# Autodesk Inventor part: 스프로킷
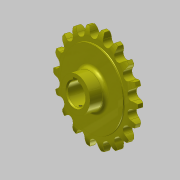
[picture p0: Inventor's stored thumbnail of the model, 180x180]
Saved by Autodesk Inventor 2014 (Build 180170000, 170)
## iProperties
Created: 2016-03
Part Number: 스프로킷
Material: 강철, 탄소
Document SubType Name: Modeling
Designer: mduedu
Density: 7.87 g/cm^3
Mass: 300.023 g
Surface Area: 127.848 cm^2
Volume: 38.1224 cm^3
Appearance: 노란색
Author: mduedu
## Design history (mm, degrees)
sketch "스케치1"
  geometry: L1 (0, 5)-(29.5, 5); L2 (29.5, 5)-(29.5, 4.1); L3 (30, 3.6)-(33.625, 3.6); L4 (40, 2)-(40, 0); L5 (40, 0)-(0, 0); L6 (0, 0)-(0, 5); L7 (0, -5)-(29.5, -5); L8 (29.5, -5)-(29.5, -4.1); L9 (30, -3.6)-(33.625, -3.6); L10 (40, -2)-(40, 0); L11 (0, 0)-(0, -5); A1 r 13.5 centre (33.625, -9.9) between (40, 2) and (33.625, 3.6); A2 r 13.5 centre (33.625, 9.9) between (33.625, -3.6) and (40, -2); A3 r 0.5 centre (30, 4.1) between (29.5, 4.1) and (30, 3.6); A4 r 0.5 centre (30, -4.1) between (30, -3.6) and (29.5, -4.1); 2 further points
  constraints: 22 end point, 8 point on circle, 6 symmetric about line, 5 tangent, 4 centre point, 4 parallel, 4 point on line, 1 equal radius, 1 horizontal, 1 perpendicular, 1 other
  dimensions: "d0" = 80 diameter of L4 L6; "d2" = 59 diameter of L2 L6; "d3" = 1.6 vertical distance of L4.start L3.end; "d4" = 3.6 distance from line of L4.end L3; "d5" = 5 distance between parallel lines of L5 L1; "d6" = 13.5 radius of A1; "d15" = 0.5 radius of A3
revolve "회전1" sketch "스케치1" stored, may be unused: angle "d7" = 90 deg
sketch "스케치2" dims "d8" = 65.2, "d11" = 80
  geometry: L1 (0, 0)-(0, 32.6); A1 r 36.57 centre (0, 0) between (-16.231, 32.771) and (0, 36.57); A2 r 3.97 centre (0, 36.57) between (-3.866, 35.665) and (0, 32.6); A3 r 12.7 centre (-16.231, 32.771) between (-3.866, 35.665) and (-5.534, 39.615); A4 r 12.7 centre (16.231, 32.771) between (5.534, 39.615) and (3.866, 35.665); A5 r 3.97 centre (0, 36.57) between (0, 32.6) and (3.866, 35.665); A6 r 40 centre (0, 0) between (5.534, 39.615) and (-5.534, 39.615); 2 further points
  constraints: 12 point on circle, 6 centre point, 4 coincident, 3 symmetric about line, 2 end point, 1 point on line, 1 tangent, 1 vertical, 1 vertical alignment, 7 other
  dimensions: "d10" = 73.14 diameter of A1; "d12" = 12.7 radius of A3
extrude "돌출1" cut sketch "스케치2" stored distance "d13" = 10; taper "d14" = 0 deg
sketch "스케치3"
  geometry: C1 r 13.5 at (0, 0); 1 further point
  constraints: 1 centre point, 1 coincident
  dimensions: "d19" = 27 diameter of C1
extrude "돌출2" join sketch "스케치3" distance "d20" = 13; taper "d21" = 0 deg
fillet "모깎기1" dims "d22" = 3
sketch "스케치4"
  geometry: L1 (-2.5, 0)-(2.5, 0); L2 (2.5, 0)-(2.5, 10.8); L3 (2.5, 10.8)-(-2.5, 10.8); L4 (-2.5, 10.8)-(-2.5, 0); C1 r 8.5 at (0, 0); 2 further points
  constraints: 8 end point, 2 coincident, 2 parallel, 1 centre point, 1 horizontal, 1 midpoint, 1 perpendicular
  dimensions: "d23" = 17 diameter of C1; "d25" = 5 distance of L2.end L3.end; "d26" = 10.8 distance of L1.end L2.end
extrude "돌출3" cut sketch "스케치4" stored distance "d27" = 8; taper "d28" = 0 deg
chamfer "모따기1" distance "d29" = 1; stored, may be unused: second distance "d30" = 2, angle "d31" = 45 deg
node "작업 평면1"
sketch "스케치5"
  geometry: L1 (13.5, 13)-(-13.5, 13) reference; 2 further points
  constraints: 1 vertical alignment
  dimensions: "d32" = 4 distance from line of point (0, 9) L1
hole "구멍1" sketch "스케치5" at (0, 9) diameter "d33" = 2.459; stored, may be unused: countersink angle "d37" = 90 deg, drill point angle "d39" = 118 deg; dims "d34" = 6, "d35" = 4, "d36" = 2, "d38" = 8
node "솔리드1"
pattern_circular "원형 패턴1" dims angle "d17" = 360 deg
